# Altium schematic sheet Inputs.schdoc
size 328 x 168 mm
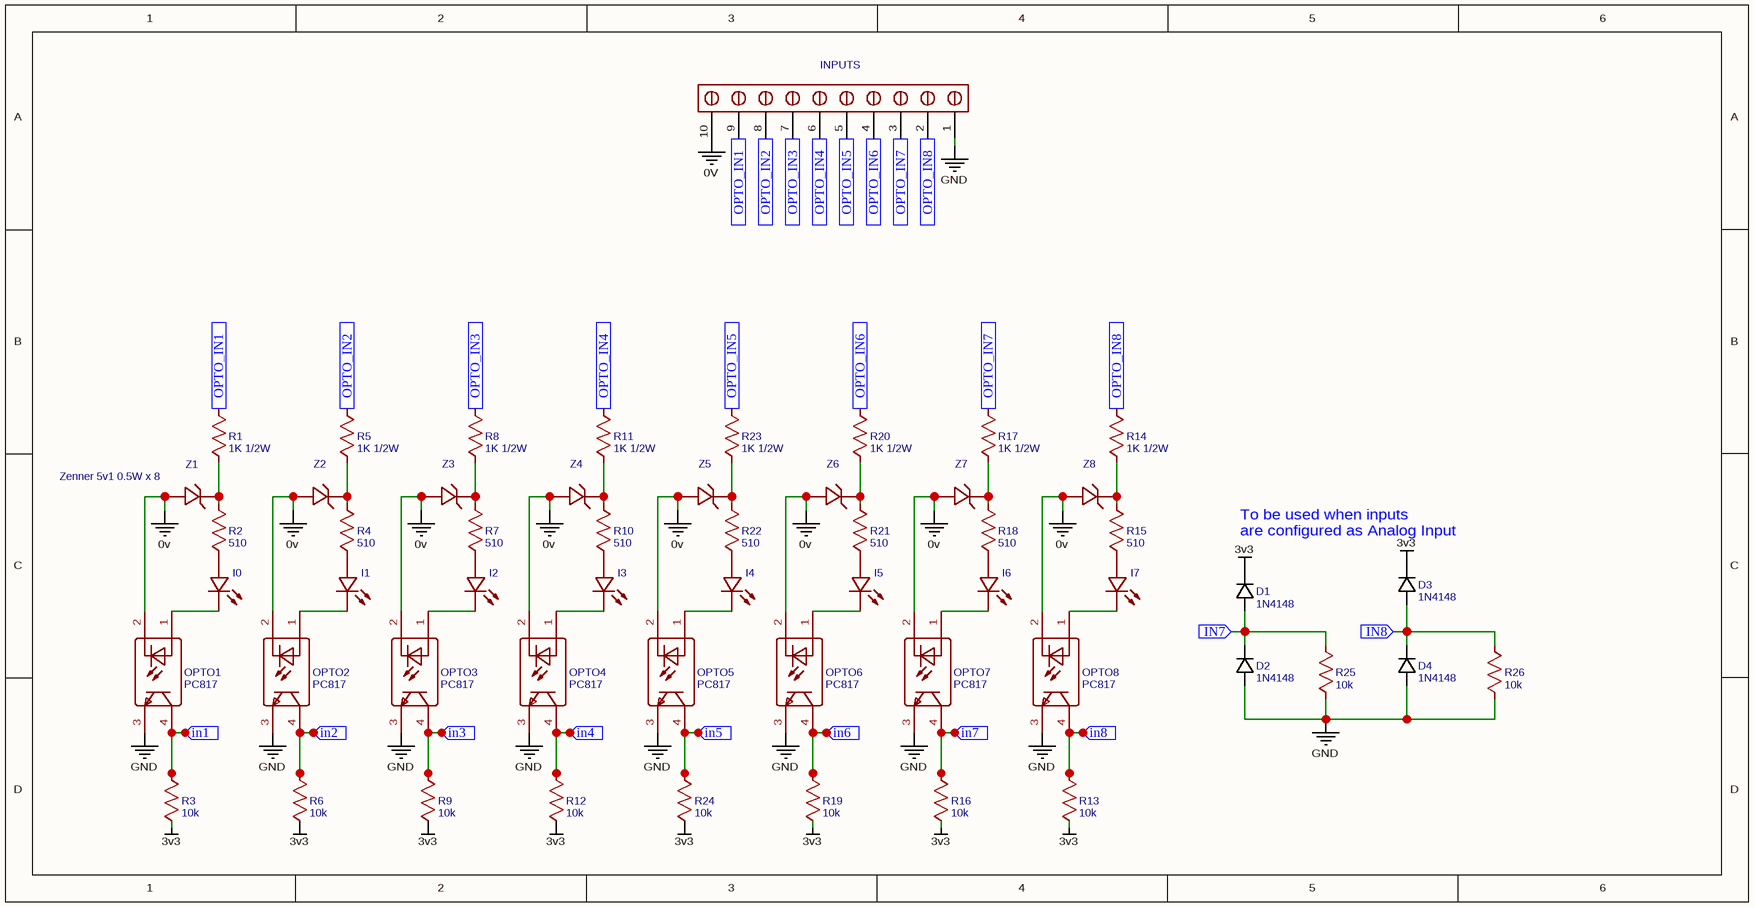
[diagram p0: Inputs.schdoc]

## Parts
D1  1N4148  [4148IN]
D2  1N4148  [4148IN]
D3  1N4148  [4148IN]
D4  1N4148  [4148IN]
I0  204-10SURD/S530-A3  [LED-3MM/2.54]  (value not drawn)
I1  204-10SURD/S530-A3  [LED-3MM/2.54]  (value not drawn)
I2  204-10SURD/S530-A3  [LED-3MM/2.54]  (value not drawn)
I3  204-10SURD/S530-A3  [LED-3MM/2.54]  (value not drawn)
I4  204-10SURD/S530-A3  [LED-3MM/2.54]  (value not drawn)
I5  204-10SURD/S530-A3  [LED-3MM/2.54]  (value not drawn)
I6  204-10SURD/S530-A3  [LED-3MM/2.54]  (value not drawn)
I7  204-10SURD/S530-A3  [LED-3MM/2.54]  (value not drawn)
INPUTS  TB008A-508-10BE  [TB008A-508-10BE]  (value not drawn)
OPTO1  PC817  [DIP-4]
OPTO2  PC817  [DIP-4]
OPTO3  PC817  [DIP-4]
OPTO4  PC817  [DIP-4]
OPTO5  PC817  [DIP-4]
OPTO6  PC817  [DIP-4]
OPTO7  PC817  [DIP-4]
OPTO8  PC817  [DIP-4]
R1  1K 1/2W  [AXIAL-0.3]
R2  510  [AXIAL-0.1]
R3  10k  [AXIAL-0.3]
R4  510  [AXIAL-0.1]
R5  1K 1/2W  [AXIAL-0.3]
R6  10k  [AXIAL-0.3]
R7  510  [AXIAL-0.1]
R8  1K 1/2W  [AXIAL-0.3]
R9  10k  [AXIAL-0.3]
R10  510  [AXIAL-0.1]
R11  1K 1/2W  [AXIAL-0.3]
R12  10k  [AXIAL-0.3]
R13  10k  [AXIAL-0.3]
R14  1K 1/2W  [AXIAL-0.3]
R15  510  [AXIAL-0.1]
R16  10k  [AXIAL-0.3]
R17  1K 1/2W  [AXIAL-0.3]
R18  510  [AXIAL-0.1]
R19  10k  [AXIAL-0.3]
R20  1K 1/2W  [AXIAL-0.3]
R21  510  [AXIAL-0.1]
R22  510  [AXIAL-0.1]
R23  1K 1/2W  [AXIAL-0.3]
R24  10k  [AXIAL-0.3]
R25  10k  [AXIAL-0.3]
R26  10k  [AXIAL-0.3]
Z1  Zenner 5v1 0.5W x 8  [DO41_Z_TH]
Z2  Zenner 1w  [DO41_Z_TH]  (value not drawn)
Z3  Zenner 1w  [DO41_Z_TH]  (value not drawn)
Z4  Zenner 1w  [DO41_Z_TH]  (value not drawn)
Z5  Zenner 1w  [DO41_Z_TH]  (value not drawn)
Z6  Zenner 1w  [DO41_Z_TH]  (value not drawn)
Z7  Zenner 1w  [DO41_Z_TH]  (value not drawn)
Z8  Zenner 1w  [DO41_Z_TH]  (value not drawn)

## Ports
in1 (in), in2 (in), in3 (in), in4 (in), in5 (in), in6 (in), in7 (in), IN7 (in), in8 (in), IN8 (in), OPTO_IN1 (in), OPTO_IN2 (in), OPTO_IN3 (in), OPTO_IN4 (in), OPTO_IN5 (in), OPTO_IN6 (in), OPTO_IN7 (in), OPTO_IN8 (in)

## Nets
0v: INPUTS.10 OPTO1.2 OPTO2.2 OPTO3.2 OPTO4.2 OPTO5.2 OPTO6.2 OPTO7.2 OPTO8.2 Z1.1(A) Z2.1(A) Z3.1(A) Z4.1(A) Z5.1(A) Z6.1(A) Z7.1(A) Z8.1(A)
3v3: D1.2 D3.2 R3.1 R6.1 R9.1 R12.1 R13.1 R16.1 R19.1 R24.1
GND: D2.1 D4.1 INPUTS.1 OPTO1.3 OPTO2.3 OPTO3.3 OPTO4.3 OPTO5.3 OPTO6.3 OPTO7.3 OPTO8.3 R25.2 R26.2
in1: OPTO1.4 R3.2 ; port in1
in2: OPTO2.4 R6.2 ; port in2
in3: OPTO3.4 R9.2 ; port in3
in4: OPTO4.4 R12.2 ; port in4
in5: OPTO5.4 R24.2 ; port in5
in6: OPTO6.4 R19.2 ; port in6
in7: D1.1 D2.2 OPTO7.4 R16.2 R25.1 ; port in7, port IN7
in8: D3.1 D4.2 OPTO8.4 R13.2 R26.1 ; port in8, port IN8
OPTO_IN1: INPUTS.9 R1.2 ; port OPTO_IN1
OPTO_IN2: INPUTS.8 R5.2 ; port OPTO_IN2
OPTO_IN3: INPUTS.7 R8.2 ; port OPTO_IN3
OPTO_IN4: INPUTS.6 R11.2 ; port OPTO_IN4
OPTO_IN5: INPUTS.5 R23.2 ; port OPTO_IN5
OPTO_IN6: INPUTS.4 R20.2 ; port OPTO_IN6
OPTO_IN7: INPUTS.3 R17.2 ; port OPTO_IN7
OPTO_IN8: INPUTS.2 R14.2 ; port OPTO_IN8
NetI0_1: I0.1(A) R2.1
NetI0_2: I0.2(K) OPTO1.1
NetI1_1: I1.1(A) R4.1
NetI1_2: I1.2(K) OPTO2.1
NetI2_1: I2.1(A) R7.1
NetI2_2: I2.2(K) OPTO3.1
NetI3_1: I3.1(A) R10.1
NetI3_2: I3.2(K) OPTO4.1
NetI4_1: I4.1(A) R22.1
NetI4_2: I4.2(K) OPTO5.1
NetI5_1: I5.1(A) R21.1
NetI5_2: I5.2(K) OPTO6.1
NetI6_1: I6.1(A) R18.1
NetI6_2: I6.2(K) OPTO7.1
NetI7_1: I7.1(A) R15.1
NetI7_2: I7.2(K) OPTO8.1
NetR1_1: R1.1 R2.2 Z1.2(K)
NetR4_2: R4.2 R5.1 Z2.2(K)
NetR7_2: R7.2 R8.1 Z3.2(K)
NetR10_2: R10.2 R11.1 Z4.2(K)
NetR14_1: R14.1 R15.2 Z8.2(K)
NetR17_1: R17.1 R18.2 Z7.2(K)
NetR20_1: R20.1 R21.2 Z6.2(K)
NetR22_2: R22.2 R23.1 Z5.2(K)

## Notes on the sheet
- (near D1) To be used when inputs
  are configured as Analog Input

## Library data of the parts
D1-D4 = 1N4148: Contributor: anoop
I0-I7 = 204-10SURD/S530-A3: BOM_Manufacturer: EVERLIGHT
INPUTS = TB008A-508-10BE: BOM_Manufacturer: CUI; Contributor: nexosrl
OPTO1-OPTO8 = PC817: BOM_Manufacturer: SHARP; BOM_Manufacturer Part: PC817X2NSZ9F(B)
R1 R5 R8 R11 R14 R17 R20 R23 = 1K 1/2W: nameAlias: Value(Ω)
R2 R4 R7 R10 R15 R18 R21 R22 = 510: nameAlias: Value(Ω)
R3 R6 R9 R12 R13 R16 R19 R24-R26 = 10k: nameAlias: Value(Ω)
Z1 = Zenner 5v1 0.5W x 8: Contributor: otanezlor
Z2-Z8 = Zenner 1w: Contributor: otanezlor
